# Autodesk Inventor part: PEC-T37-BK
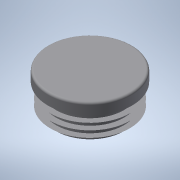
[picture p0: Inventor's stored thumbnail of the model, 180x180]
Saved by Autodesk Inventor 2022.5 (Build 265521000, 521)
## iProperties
Created: 2017-10
Part Number: PEC-T37-BK
Material: 一般
Document SubType Name: Modeling
Designer: imaocorp
Density: 1 g/cm^3
Appearance: 既定
Author: imaocorp
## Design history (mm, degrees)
node "PEC-T37-BK.x_t1"
node "PEC-T37-BK"
node "Base1"
